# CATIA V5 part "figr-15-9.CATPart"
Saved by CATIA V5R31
Part number: Part1
Bounding box of the stored display mesh (mm): x -50 to 50, y -32.5 to 33.5, z -52 to 1
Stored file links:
  D:\PROJECTS\Project 2021\US EDITION\CATIA V5 6R 2021\Resources\Part Files\c15_catia_v5_6r2021_prt\figr-15-9.CATPart
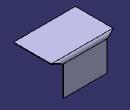
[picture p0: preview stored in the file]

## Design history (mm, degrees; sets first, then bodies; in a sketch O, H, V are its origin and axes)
SheetMetalParameters1: Thickness 1, BendRadius 4, KFactor 0.475772 {= log(min(100,max(20*SheetMetalParameters1.BendRadius,SheetMetalParameters1.Thickness)/SheetMetalParameters1.Thickness))/log(100)/2}, ReliefRadialLength 4, ReliefAxialLength 4, MinimumBendRadius 0
Body1 (main body)
  Sketch1 on xy-plane, origin (0, 0, 0), H (1, 0, 0), V (0, 1, 0)
    line L1 (-50, 32.5) -> (50, 32.5)
    line L2 (50, 32.5) -> (50, -32.5)
    line L3 (50, -32.5) -> (-50, -32.5)
    line L4 (-50, -32.5) -> (-50, 32.5)
    length L1 = 100
    length L2 = 65
    horizontal: L1 H, L3 H
    vertical: L2 V, L4 V
    symmetry: L4 L2 V, L1 L3 H
  Wall1: Thickness 1, Profile Sketch1
  d_NewWallOnEdge1: NewWallOnEdge_Edge edge [face of Wall1 | face of Wall1], NewWallOnEdge_Length 53, NewWallOnEdge_HeightLimitOffset 0, NewWallOnEdge_WidthOffset1 -15, NewWallOnEdge_WidthOffset2 -15, NewWallOnEdge_Angle 90, NewWallOnEdge_BendRadiusValue 4 {= SheetMetalParameters1.BendRadius}, NewWallOnEdge_BendTable SheetMetalParameters1, KFacteur 0.475772 {= log(min(100,max(20*d_NewWallOnEdge1.Radius,SheetMetalParameters1.Thickness)/SheetMetalParameters1.Thickness))/log(100)/2}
